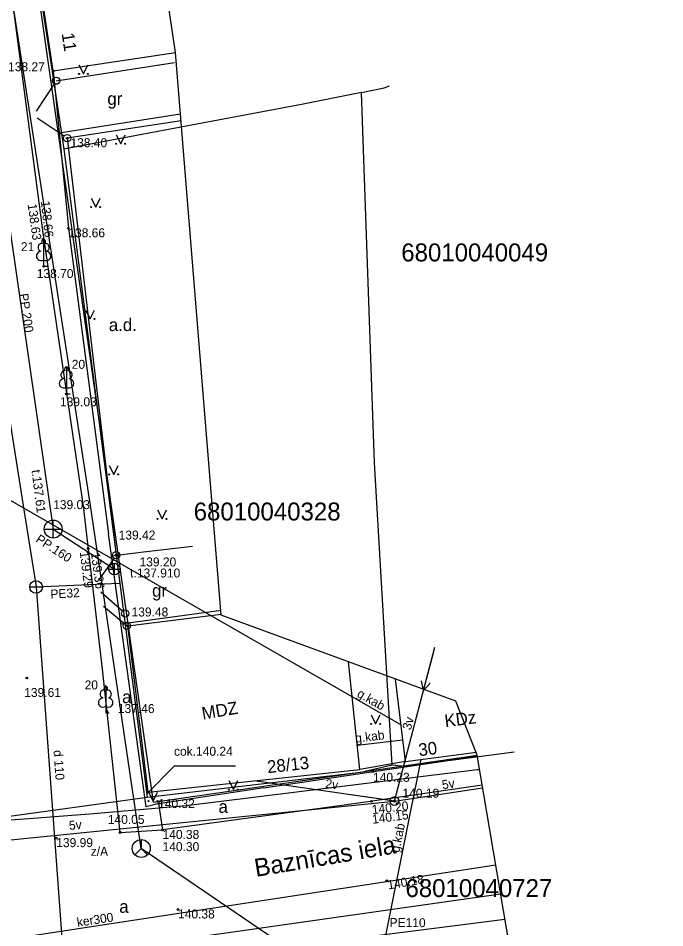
# Model space of a CAD drawing. Extents: x 728710 to 728960, y 272811 to 273475.
# Drawn here: x 728802 to 728838, y 273212.2 to 273262.9 of the extents above; entities that cross this region are included whole.
import ezdxf

# ---------------------------------------------------------------- set-up
doc = ezdxf.new("R2010")
doc.units = 0
for name, color, linetype in [('54', 7, 'Continuous'), ('Level 15', 7, 'Continuous'), ('Level 17', 7, 'Continuous'), ('Level 18', 7, 'Continuous'), ('Level 20', 7, 'Continuous'), ('Level 21', 7, 'Continuous'), ('Level 23', 7, 'Continuous'), ('Level 27', 7, 'Continuous'), ('Level 28', 7, 'Continuous'), ('Level 29', 7, 'Continuous'), ('Level 3', 7, 'Continuous'), ('Level 39', 7, 'Continuous'), ('Level 4', 7, 'Continuous'), ('Level 41', 7, 'Continuous'), ('Level 42', 7, 'Continuous'), ('Level 43', 7, 'Continuous'), ('Level 46', 7, 'Continuous'), ('Level 48', 7, 'Continuous'), ('Level 50', 7, 'Continuous'), ('Level 53', 7, 'Continuous'), ('Level 54', 7, 'Continuous'), ('Level 55', 7, 'Continuous'), ('Level 56', 7, 'Continuous'), ('Level 57', 7, 'Continuous'), ('Level 58', 7, 'Continuous'), ('Level 59', 7, 'Continuous'), ('Level 60', 7, 'Continuous'), ('Level 62', 7, 'Continuous'), ('Level 9', 7, 'Continuous'), ('RAMI_UZMR_####_####_#', 7, 'Continuous'), ('RELJ_NOGA_####_####_#', 7, 'Continuous'), ('ROBZ_ELEM_####_####_#', 7, 'Continuous'), ('ROBZ_KADS_####_TKST_#', 7, 'Continuous'), ('ROBZ_UZMR_####_####_#', 7, 'Continuous'), ('SAKT_VADV_PKAB_TKST_#', 7, 'Continuous'), ('TERT_KOKR_####_####_#', 7, 'Continuous'), ('TERT_KONT_####_####_#', 7, 'Continuous')]:
    doc.layers.add(name, color=color, linetype=linetype)

msp = doc.modelspace()

# ---------------------------------------------------------------- linework, layer by layer
at = {"layer": 'Level 15'}
msp.add_circle((728822.972, 273219.263), 0.25, dxfattribs=at)
at = {"layer": 'Level 17'}
for p, q in [((728803.013, 273231.194), (728807.639, 273231.4)), ((728804.594, 273209.577), (728829.118, 273212.697))]:
    msp.add_line(p, q, dxfattribs=at)
for points in [[(728797.092, 273268.609), (728802.352, 273235.373)], [(728802.352, 273235.373), (728803.013, 273231.194)], [(728803.013, 273231.194), (728804.591, 273209.598), (728804.594, 273209.577)]]:
    msp.add_lwpolyline(points, dxfattribs=at)
at = {"layer": 'Level 18'}
msp.add_lwpolyline([(728775.408, 273206.499), (728828.88, 273214.109)], dxfattribs=at)
at = {"layer": 'Level 20'}
for p, q in [((728824.585, 273225.422), (728825.155, 273227.598)), ((728824.585, 273225.422), (728824.469, 273225.969)), ((728824.585, 273225.422), (728824.953, 273225.842)), ((728821.331, 273219.5), (728820.497, 273219.621)), ((728822.971, 273219.263), (728821.331, 273219.5))]:
    msp.add_line(p, q, dxfattribs=at)
at = {"layer": 'Level 21'}
for p, q in [((728822.971, 273219.263), (728825.218, 273227.84)), ((728822.972, 273219.263), (728815.15, 273220.395)), ((728822.971, 273219.263), (728827.881, 273220.012)), ((728799.963, 273216.945), (728822.971, 273219.263))]:
    msp.add_line(p, q, dxfattribs=at)
at = {"layer": 'Level 23'}
for p, q in [((728799.123, 273267.839), (728803.964, 273234.42)), ((728803.964, 273234.42), (728807.373, 273232.192))]:
    msp.add_line(p, q, dxfattribs=at)
msp.add_lwpolyline([(728828.61, 273215.701), (728797.551, 273210.954), (728774.123, 273207.246)], dxfattribs=at)
at = {"layer": 'Level 27'}
msp.add_lwpolyline([(728823.58, 273221.48), (728821.045, 273221.026)], dxfattribs=at)
at = {"layer": 'Level 28'}
msp.add_lwpolyline([(728811.083, 273257.166), (728804.741, 273256.2), (728807.468, 273232.966)], dxfattribs=at)
at = {"layer": 'Level 29'}
for p, q in [((728803.964, 273233.92), (728803.964, 273234.92)), ((728803.464, 273234.42), (728804.464, 273234.42)), ((728807.373, 273231.872), (728807.373, 273232.512)), ((728807.053, 273232.192), (728807.693, 273232.192))]:
    msp.add_line(p, q, dxfattribs=at)
for centre, radius in [((728803.964, 273234.42), 0.5), ((728807.373, 273232.192), 0.32)]:
    msp.add_circle(centre, radius, dxfattribs=at)
at = {"layer": 'Level 3'}
for p, q in [((728803.969, 273259.941), (728802.415, 273270.14)), ((728803.969, 273259.941), (728810.773, 273260.978)), ((728808.129, 273229.035), (728813.323, 273229.674)), ((728809.255, 273219.763), (728808.129, 273229.035)), ((728821.045, 273221.026), (728820.402, 273227.026)), ((728823.58, 273221.48), (728823.034, 273226.063)), ((728823.58, 273221.48), (728827.548, 273221.984)), ((728809.255, 273219.763), (728821.045, 273221.026))]:
    msp.add_line(p, q, dxfattribs=at)
at = {"layer": 'Level 39'}
for p, q in [((728802.662, 273231.194), (728803.364, 273231.194)), ((728803.012, 273231.194), (728803.012, 273231.195))]:
    msp.add_line(p, q, dxfattribs=at)
msp.add_circle((728803.013, 273231.194), 0.351, dxfattribs=at)
at = {"layer": 'Level 4'}
for p, q in [((728804.13, 273259.398), (728810.723, 273260.403)), ((728809.151, 273218.941), (728807.037, 273234.155)), ((728807.206, 273232.935), (728808.997, 273233.145)), ((728808.997, 273233.145), (728811.717, 273233.464)), ((728821.197, 273220.827), (728827.584, 273221.772)), ((728815.689, 273220.012), (728821.197, 273220.827)), ((728815.689, 273220.012), (728809.721, 273219.103)), ((728827.856, 273220.162), (728821.36, 273219.206)), ((728809.721, 273219.103), (728809.151, 273218.941)), ((728820.046, 273219.013), (728810.047, 273217.657)), ((728821.36, 273219.206), (728820.046, 273219.013)), ((728807.694, 273217.517), (728810.047, 273217.657)), ((728810.047, 273217.657), (728810.047, 273217.657))]:
    msp.add_line(p, q, dxfattribs=at)
for points in [[(728803.413, 273250.931), (728800.916, 273269.685), (728796.563, 273300.793)], [(728803.969, 273259.941), (728804.808, 273251.175), (728807.037, 273234.155)], [(728804.298, 273256.5), (728811.052, 273257.544)], [(728805.653, 273235.703), (728803.413, 273250.931)], [(728807.687, 273217.516), (728806.709, 273226.611), (728805.653, 273235.703)], [(728807.733, 273229.146), (728813.314, 273229.909)], [(728809.835, 273219.135), (728810.047, 273217.657)]]:
    msp.add_lwpolyline(points, dxfattribs=at)
at = {"layer": 'Level 41'}
for points in [[(728806.045, 273235.742), (728805.58, 273238.737), (728804.235, 273247.399), (728800.223, 273273.247), (728790.96, 273338.691), (728788.283, 273357.608), (728788.02, 273359.462)], [(728819.726, 273208.522), (728819.527, 273209.009), (728819.326, 273209.502), (728808.867, 273216.627), (728806.045, 273235.742)]]:
    msp.add_lwpolyline(points, dxfattribs=at)
at = {"layer": 'Level 42'}
for points in [[(728796.953, 273234.834), (728797.171, 273233.12), (728798.705, 273220.412), (728798.759, 273219.965), (728799.063, 273219.076), (728799.29, 273218.573), (728800.035, 273218.111), (728802.6, 273218.3), (728805.991, 273218.55), (728811.368, 273219.028), (728821.256, 273220.241)], [(728821.256, 273220.241), (728827.578, 273221.017), (728827.708, 273221.035)]]:
    msp.add_lwpolyline(points, dxfattribs=at)
at = {"layer": 'Level 43'}
for p, q in [((728804.021, 273259.231), (728803.024, 273257.706)), ((728804.574, 273256.311), (728803.07, 273257.31)), ((728807.353, 273232.803), (728806.489, 273231.578)), ((728807.82, 273229.853), (728806.611, 273230.908)), ((728808.063, 273229.027), (728806.771, 273230.109))]:
    msp.add_line(p, q, dxfattribs=at)
for centre in [(728804.13, 273259.398), (728804.741, 273256.2), (728807.468, 273232.966), (728807.971, 273229.721), (728808.063, 273229.027)]:
    msp.add_circle(centre, 0.202, dxfattribs=at)
at = {"layer": 'Level 46'}
msp.add_line((728808.867, 273216.627), (728809.221, 273216.274), dxfattribs=at)
msp.add_lwpolyline([(728808.867, 273217.127), (728808.867, 273216.627), (728808.514, 273216.274)], dxfattribs=at)
msp.add_circle((728808.867, 273216.627), 0.5, dxfattribs=at)
at = {"layer": 'Level 48'}
for centre in [(728803.969, 273259.941), (728804.739, 273256.193), (728804.808, 273251.175), (728803.413, 273250.566), (728803.434, 273249.061), (728804.703, 273241.956), (728805.918, 273233.334), (728807.468, 273232.966), (728808.129, 273229.035), (728802.492, 273226.122), (728806.948, 273224.255), (728821.775, 273220.904), (728809.851, 273219.137), (728821.69, 273219.254), (728822.972, 273219.263), (728807.694, 273217.517), (728810.047, 273217.657), (728804.134, 273217.202), (728822.542, 273214.834), (728810.917, 273213.228)]:
    msp.add_circle(centre, 0.05, dxfattribs=at)
at = {"layer": 'Level 9'}
msp.add_lwpolyline([(728809.209, 273219.71), (728810.717, 273221.232), (728814.116, 273221.232)], dxfattribs=at)
at = {"layer": 'RAMI_UZMR_####_####_#'}
for points in [[(728838.026, 273158.297), (728833.202, 273166.507), (728833.235, 273168.344), (728821.579, 273179.812), (728818.749, 273194.545), (728819.331, 273202.951), (728829.731, 273204.761), (728829.577, 273209.987), (728827.575, 273221.822), (728826.396, 273224.831), (728813.325, 273229.618), (728810.773, 273260.978), (728802.611, 273315.901)], [(728791.56, 273241.761), (728823.339, 273223.506)], [(728820.9, 273222.376), (728823.437, 273222.679)], [(728824.437, 273221.588), (728821.531, 273207.064)]]:
    msp.add_lwpolyline(points, dxfattribs=at)
at = {"layer": 'ROBZ_ELEM_####_####_#'}
for points in [[(728809.55, 273219.213), (728789.366, 273361.101)], [(728809.55, 273219.213), (728827.575, 273221.822)]]:
    msp.add_lwpolyline(points, dxfattribs=at)
at = {"layer": 'ROBZ_UZMR_####_####_#'}
for p, q in [((728802.394, 273269.955), (728803.943, 273259.665)), ((728803.943, 273259.665), (728804.562, 273255.582)), ((728821.131, 273258.741), (728822.393, 273259.008)), ((728822.393, 273259.008), (728822.703, 273259.118)), ((728821.131, 273258.741), (728817.792, 273258.065)), ((728821.86, 273238.116), (728821.131, 273258.741)), ((728817.792, 273258.065), (728804.562, 273255.582)), ((728804.562, 273255.582), (728808.01, 273228.814)), ((728822.838, 273221.28), (728821.86, 273238.116)), ((728808.01, 273228.814), (728809.201, 273219.485)), ((728823.567, 273221.218), (728829.639, 273222.013)), ((728809.201, 273219.485), (728821.09, 273220.875)), ((728821.09, 273220.875), (728822.838, 273221.28)), ((728822.838, 273221.28), (728823.567, 273221.218)), ((728797.009, 273217.805), (728809.201, 273219.485))]:
    msp.add_line(p, q, dxfattribs=at)
at = {"layer": 'TERT_KONT_####_####_#'}
for p, q in [((728805.401, 273260.279), (728805.651, 273259.779)), ((728805.651, 273259.779), (728805.901, 273260.279)), ((728807.475, 273256.389), (728807.725, 273255.889)), ((728807.725, 273255.889), (728807.975, 273256.389)), ((728806.087, 273252.859), (728806.337, 273252.359)), ((728806.337, 273252.359), (728806.587, 273252.859)), ((728803.434, 273249.408), (728803.434, 273249.061)), ((728803.434, 273249.061), (728803.634, 273249.061)), ((728805.769, 273246.624), (728806.019, 273246.124)), ((728806.019, 273246.124), (728806.269, 273246.624)), ((728804.705, 273242.31), (728804.705, 273241.963)), ((728804.705, 273241.963), (728804.905, 273241.963)), ((728807.083, 273237.968), (728807.333, 273237.468)), ((728807.333, 273237.468), (728807.583, 273237.968)), ((728809.778, 273235.484), (728810.028, 273234.984)), ((728810.028, 273234.984), (728810.278, 273235.484)), ((728806.889, 273224.527), (728806.889, 273224.18)), ((728806.889, 273224.18), (728807.089, 273224.18)), ((728821.667, 273224.067), (728821.917, 273223.567)), ((728821.917, 273223.567), (728822.167, 273224.067)), ((728813.748, 273220.41), (728813.998, 273219.91)), ((728813.998, 273219.91), (728814.248, 273220.41)), ((728809.273, 273219.765), (728809.523, 273219.265)), ((728809.523, 273219.265), (728809.773, 273219.765))]:
    msp.add_line(p, q, dxfattribs=at)
for points in [[(728803.434, 273250.561), (728803.434, 273249.408)], [(728803.524, 273250.329), (728803.523, 273250.33)], [(728804.705, 273243.463), (728804.705, 273242.31)], [(728804.795, 273243.231), (728804.794, 273243.232)], [(728806.889, 273225.68), (728806.889, 273224.527)], [(728806.978, 273225.448), (728806.977, 273225.449)]]:
    msp.add_lwpolyline(points, dxfattribs=at)
for centre, radius in [((728805.401, 273259.779), 0.028), ((728805.901, 273259.779), 0.0263), ((728807.475, 273255.889), 0.028), ((728807.975, 273255.889), 0.0263), ((728806.087, 273252.358), 0.028), ((728806.587, 273252.358), 0.0263), ((728805.769, 273246.124), 0.028), ((728806.269, 273246.124), 0.0263), ((728807.083, 273237.468), 0.028), ((728807.583, 273237.468), 0.0263), ((728809.778, 273234.983), 0.028), ((728810.278, 273234.983), 0.0263), ((728821.667, 273223.567), 0.028), ((728822.167, 273223.567), 0.0263), ((728813.748, 273219.909), 0.028), ((728814.248, 273219.909), 0.0263), ((728809.273, 273219.265), 0.028), ((728809.773, 273219.265), 0.0263)]:
    msp.add_circle(centre, radius, dxfattribs=at)
for centre, major_axis, ratio, start_param, end_param in [((728803.306, 273250.116), (-0.039, -0.212), 0.861323, 3.141593, 6.283185), ((728803.434, 273250.411), (0, -0.15), 0.707107, 3.14537, 5.287485), ((728803.434, 273250.411), (0, -0.15), 0.707107, 0.995701, 3.137816), ((728803.562, 273250.116), (0.039, -0.212), 0.861323, 0, 3.141593), ((728803.344, 273249.654), (0.307, 0.095), 0.814445, 1.570796, 4.752015), ((728803.524, 273249.654), (-0.307, 0.095), 0.814445, 1.531171, 4.712389), ((728804.577, 273243.018), (-0.039, -0.212), 0.861323, 3.141593, 6.283185), ((728804.705, 273243.313), (0, -0.15), 0.707107, 3.14537, 5.287485), ((728804.705, 273243.313), (0, -0.15), 0.707107, 0.995701, 3.137816), ((728804.833, 273243.018), (0.039, -0.212), 0.861323, 0, 3.141593), ((728804.615, 273242.556), (0.307, 0.095), 0.814445, 1.570796, 4.752015), ((728804.795, 273242.556), (-0.307, 0.095), 0.814445, 1.531171, 4.712389), ((728806.76, 273225.236), (-0.039, -0.212), 0.861323, 3.141593, 6.283185), ((728806.889, 273225.53), (0, -0.15), 0.707107, 3.14537, 5.287485), ((728806.888, 273225.53), (0, -0.15), 0.707107, 0.995701, 3.137816), ((728807.017, 273225.236), (0.039, -0.212), 0.861323, 0, 3.141593), ((728806.799, 273224.773), (0.307, 0.095), 0.814445, 1.570796, 4.752015), ((728806.978, 273224.773), (-0.307, 0.095), 0.814445, 1.531171, 4.712389)]:
    msp.add_ellipse(centre, major_axis=major_axis, ratio=ratio, start_param=start_param, end_param=end_param, dxfattribs=at)

# ---------------------------------------------------------------- texts
at = {"layer": '54'}
msp.add_text('z/A', height=0.5, dxfattribs=at).set_placement((728806.057, 273216.218))
at = {"layer": 'Level 50'}
msp.add_text('cok.140.24', height=0.5, dxfattribs=at).set_placement((728810.692, 273221.791))
at = {"layer": 'Level 53'}
for s, rotation, p in [('3v', 75.066, (728823.878, 273223.194)), ('2v', 351.768, (728819.097, 273220.011)), ('5v', 8.673, (728825.655, 273219.921)), ('5v', 4.487, (728804.863, 273217.659))]:
    msp.add_text(s, height=0.5, rotation=rotation, dxfattribs=at).set_placement(p)
at = {"layer": 'Level 54'}
msp.add_text('Baznīcas iela', height=1, rotation=9.6084, dxfattribs=at).set_placement((728815.258, 273215.039))
at = {"layer": 'Level 55'}
for s, rotation, p in [('PE32', 3.1849, (728803.824, 273230.544)), ('d 110', 274.1791, (728803.979, 273222.089)), ('PE110', 359.6578, (728822.698, 273212.253))]:
    msp.add_text(s, height=0.5, rotation=rotation, dxfattribs=at).set_placement(p)
at = {"layer": 'Level 56'}
for s, p in [('139.03', (728803.964, 273235.529)), ('139.20', (728808.773, 273232.338))]:
    msp.add_text(s, height=0.5, dxfattribs=at).set_placement(p)
at = {"layer": 'Level 57'}
for s, p in [(' 138.27', (728801.265, 273259.925)), (' 138.40', (728804.739, 273255.693)), ('138.66', (728804.808, 273250.675)), (' 138.70', (728802.864, 273248.403)), (' 139.03', (728804.159, 273241.261)), (' 139.42', (728807.425, 273233.836)), (' 139.48', (728808.142, 273229.551)), (' 139.61', (728802.165, 273225.067)), ('137.46', (728807.565, 273224.173)), ('140.23', (728821.775, 273220.342)), (' 140.19', (728823.231, 273219.458)), ('140.32', (728809.807, 273218.878)), ('140.05', (728807.007, 273217.995)), ('140.38', (728810.055, 273217.158)), ('139.99', (728804.134, 273216.702)), ('140.30', (728810.055, 273216.478)), ('140.38', (728810.917, 273212.728))]:
    msp.add_text(s, height=0.5, dxfattribs=at).set_placement(p)
for s, rotation, p in [('138.63', 278.023, (728802.538, 273252.509)), ('138.66', 276.1106, (728803.278, 273252.68)), ('139.29', 277.1905, (728805.443, 273233.141)), ('139.36', 277.7487, (728806.064, 273233.086)), ('140.20', 6.464, (728821.741, 273218.54)), ('140.15', 7.6254, (728821.756, 273217.999)), ('140.18', 9.6555, (728822.626, 273214.341))]:
    msp.add_text(s, height=0.5, rotation=rotation, dxfattribs=at).set_placement(p)
at = {"layer": 'Level 58'}
for s, p in [('gr', (728806.982, 273258.048)), ('gr', (728809.473, 273230.647)), ('a', (728807.804, 273224.723)), ('a', (728813.171, 273218.61)), ('a', (728807.645, 273213.043))]:
    msp.add_text(s, height=0.7, dxfattribs=at).set_placement(p)
at = {"layer": 'Level 59'}
for s, rotation, p in [('MDZ', 9.643, (728812.299, 273223.8)), ('KDz', 7.2367, (728825.804, 273223.383))]:
    msp.add_text(s, height=0.7, rotation=rotation, dxfattribs=at).set_placement(p)
at = {"layer": 'Level 60'}
for s, rotation, p in [('PP.200', 278.2424, (728802.068, 273247.51)), ('t.137.61', 277.2375, (728802.756, 273237.697)), ('PP.160', 326.8328, (728802.948, 273233.74)), ('ker300', 8.69, (728805.324, 273212.259))]:
    msp.add_text(s, height=0.5, rotation=rotation, dxfattribs=at).set_placement(p)
msp.add_text('t.137.910', height=0.5, dxfattribs=at).set_placement((728808.253, 273231.723))
at = {"layer": 'Level 62'}
for s, rotation, p in [('11', 278.663, (728804.434, 273262.02)), ('30', 7.236, (728824.351, 273221.764)), ('28/13', 6.114, (728815.917, 273220.82))]:
    msp.add_text(s, height=0.7, rotation=rotation, dxfattribs=at).set_placement(p)
at = {"layer": 'RELJ_NOGA_####_####_#'}
for s, p in [('21', (728802.167, 273249.902)), ('20', (728804.997, 273243.347)), ('20', (728805.715, 273225.488))]:
    msp.add_text(s, height=0.5, dxfattribs=at).set_placement(p)
at = {"layer": 'ROBZ_KADS_####_TKST_#'}
for s, p in [('68010040049', (728823.349, 273249.331)), ('68010040328', (728811.79, 273234.898)), ('68010040727', (728823.581, 273213.92))]:
    msp.add_text(s, height=1, dxfattribs=at).set_placement(p)
at = {"layer": 'SAKT_VADV_PKAB_TKST_#'}
for rotation, p in [(330.1247, (728820.84, 273225.114)), (6.8237, (728820.813, 273222.516)), (78.6848, (728823.241, 273216.375))]:
    msp.add_text('g.kab', height=0.5, rotation=rotation, dxfattribs=at).set_placement(p)
at = {"layer": 'TERT_KOKR_####_####_#'}
msp.add_text('a.d.', height=0.7, dxfattribs=at).set_placement((728807.064, 273245.451))

doc.saveas('drawing.dxf')
